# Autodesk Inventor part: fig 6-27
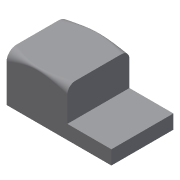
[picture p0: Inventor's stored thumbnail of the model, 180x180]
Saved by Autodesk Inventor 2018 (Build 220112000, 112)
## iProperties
Created: 2004-05
Part Number: fig 6-27
Document SubType Name: Modeling
Designer: CADCIM Technologies
Manufacturer: Standard
Standards Organization: Custom
Density: 1 g/cm^3
Material: Generic
Appearance: Default
Author: CADCIM Technologies
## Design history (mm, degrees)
node "Sketch1"
sketch "Sketch2"
  geometry: L1 (0.098, 47.711)-(0.098, 0.049); L2 (0.098, 0.049)-(-105.483, 0.049); L3 (-105.483, 0.049)-(-105.483, 14.192); L4 (-105.483, 14.192)-(-61.139, 14.192); L5 (-61.139, 14.192)-(-61.139, 47.711); L6 (-61.139, 47.711)-(0.098, 47.711)
  constraints: 12 end point, 3 parallel, 2 perpendicular, 1 vertical
extrude "Extrusion1" new body sketch "Sketch2" stored distance "d0" = 62.5; taper "d1" = 0 deg
fillet "Fillet9" dims "d61" = 10, "d62" = 8, "d63" = 2, "d64" = 5
fillet "Fillet10" dims "d65" = 8, "d66" = 10, "d67" = 2, "d68" = 5
body "Solid1"
